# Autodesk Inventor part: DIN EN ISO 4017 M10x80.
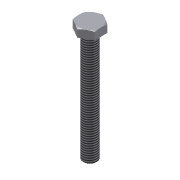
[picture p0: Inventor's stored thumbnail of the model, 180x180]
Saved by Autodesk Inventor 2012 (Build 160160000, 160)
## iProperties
Created: 2001-01
Part Number: DIN EN ISO 4017 M10x80.
Material: Steel, Mild
Document SubType Name: Modeling
Description: Sechskantschraube DIN EN ISO 4017 - M10x80.
Standard: DIN EN ISO 4017
Density: 7.86 g/cm^3
Company: CAD-Verlag
+MSCProtocol1+ProtocolID: P00040924082636040
+MSCProtocol2+Protocol: P00040924082636040<@PID>[Version]<@EL>Version=2.2<@EL>[Data]<@EL>mass=0.060436329{kg<@EL>b=77{mm<@EL>c=0.6{mm<@EL>dw=15{mm<@EL>r=0.4{mm<@EL>s=16{mm<@EL>d=10{mm<
Control State: 0
Master: False
Checked Out: False
Shininess: 20.0
Length Units: 11269
Angle Units: 11279
Time Units: 11290
Mass Units: 11283
Length Display Precision: 3
Angle Display Precision: 2
BOM1: Sechskantschraube
BOM2: M10x80
BOM3: DIN EN ISO 4017
Density: 7.859999999999999
Volumn: 5.59798751986722
Area: 24.439342304675858
PropertySet Name: Model Information
Author: Jürgen Kronas
Revision Number: 1
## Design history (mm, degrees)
node "WorkPlane1"
node "Sketch1"
node "WorkPoint1"
extrude "ExtrusionBlind1" new body distance "d2" = 80 (= prf_l); taper "d3" = 0 deg
  node "Sketch2" dims "d1" = 10 (= prf_d)
chamfer "Chamfer1" distance "d4" = 0.75 (= msp_z); stored, may be unused: second distance "d5" = 0.75 (= msp_z), angle "d31" = 45 deg
node "WorkAxis1"
sketch "Sketch3" dims "d8" = 15 (= prf_dw)
  geometry: C1 r 5 at (0, 0) reference
  constraints: 1 other
extrude "ExtrusionBlind2" join sketch "Sketch3" distance "d9" = 0.6 (= prf_c); taper "d10" = 0 deg
sketch "Sketch4" dims "d13" = 16 (= prf_s)
  geometry: L1 (-8, 4.619)-(-8, -4.619); L2 (0, 9.238)-(-8, 4.619); L3 (8, 4.619)-(0, 9.238); L4 (8, -4.619)-(8, 4.619); L5 (0, -9.238)-(8, -4.619); L6 (-8, -4.619)-(0, -9.238); C1 r 7.5 at (0, 0) reference; C2 r 5 at (0, 0) reference; C3 r 4.25 at (0, 0) reference
  constraints: 12 end point, 4 vertical, 2 parallel, 7 other
extrude "ExtrusionBlind3" join sketch "Sketch4" distance "d14" = 5.8 (= -prf_c + prf_k); taper "d15" = 0 deg
sketch "Sketch5"
  geometry: L1 (-9.238, 5.685)-(-8, 6.4); L2 (0, -50.981)-(0, 0.981); L3 (0, -62.457)-(0, 17.876) reference; L4 (-8, 6.4)-(-9.238, 6.4); L5 (-9.238, 6.4)-(-9.238, 5.685); L6 (-9.238, 0.6)-(-9.238, 6.4) reference
  constraints: 8 end point, 2 perpendicular
  dimensions: "d20" = 0 distance between parallel lines of L6 L5; "d21" = 0 distance from line of L6.end L4; "d22" = 8 distance from line of L3 L1.end (= 0.5 x prf_s); "d23" = 60 deg angle of L6 L1
revolve "RevolutionFull1" sketch "Sketch5" stored, may be unused: angle "d18" = 360 deg
fillet "Fillet1" dims "d19" = 0.4 (= prf_r)
feature "Ms_Thread" dims "d25" = 0, "prf_b" = 77
node "MSC_A1"
node "MSC_PF1"
node "MSC_PT1"
node "Volumenkörper1"
node "Volumenkörpern"
node "Oberflächenkörpern"
other parameters: "prf_p" = 1.5 [user parameter; used in 1 equation term], "prf_l" = 80 [user parameter; used in 1 equation term], "prf_k" = 6.4 [user parameter; used in 1 equation term], "prf_s" = 16 [user parameter; used in 2 equation terms], "prf_r" = 0.4 [user parameter; used in 1 equation term], "prf_dw" = 15 [user parameter; used in 1 equation term], "prf_c" = 0.6 [user parameter; used in 2 equation terms], "msp_z" = 0.75 (= 0.5 x prf_p) [user parameter; used in 2 equation terms], "d6" = 0, "d7" = 15 (derived), "d11" = 0, "d12" = 17 (derived), "d16" = 30 deg (derived), "d28" = 0, "d29" = 0, "d30" = 0
